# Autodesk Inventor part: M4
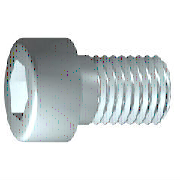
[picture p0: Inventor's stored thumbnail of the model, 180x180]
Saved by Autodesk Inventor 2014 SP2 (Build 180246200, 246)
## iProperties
IsCustomPart: 0
Created: 2016-04
Part Number: M4
Material: 강철, 연강
Description: 6각머리 태핑 나사
Document SubType Name: Modeling
Standard: KS B 1003
Designer: mdu
Standards Organization: KS
Language: ko-KR
Size Designation: M 4 x 10
Categories: <MemberInstance><Categories><Category DisplayName="조임쇠" InternalName="e4da775c-781d-43d5-af7c-5136215cf5a6" Mnemonic="FSTN"><Category DisplayName="볼트" InternalN
Density: 7.86 g/cm^3
Mass: 2.0371 g
Surface Area: 3.0572 cm^2
Volume: 0.259174 cm^3
Appearance: 금속 1800F 열
Author: mdu
Revision Number: 1
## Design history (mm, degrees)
sketch "스케치1"
  geometry: L1 (-1, 0)-(10, 0); L2 (10, 0)-(10, 2); L3 (10, 2)-(1.75, 2); L4 (1.75, 2)-(1.32, 2); L5 (1.32, 2)-(0, 2); L6 (0, 2)-(0, 3.5); L7 (0, 3.5)-(-4, 3.5); L8 (-4, 3.5)-(-4, 1.732); L9 (-4, 1.732)-(-2, 1.732); L10 (-2, 1.732)-(-1, 0); L11 (-6.8, 0)-(12.8, 0) reference; L12 (0, -0.7)-(0, 4.2) reference; L13 (1.75, 2)-(0, 2)
  constraints: 22 end point, 6 parallel, 2 collinear, 2 perpendicular, 1 horizontal, 1 point on line
  dimensions: "d1" = 8.25 distance from line of L3.end L2 (= GEL); "d2" = 0.42952 distance of L4.end L3.end (computed from GAL); "d3" = 4 distance between parallel lines of L8 L6 (= KOH); "d4" = 2 distance of L8.end L9.end (= INTI); "d5" = 60 deg angle of L10 L1; "d6" = 4 diameter of L3 L1 (= GD); "d7" = 4 diameter of L5 L1 (= BDM); "d8" = 3.4641 diameter of L9 L1 (= 1.1547 x SW); "d9" = 7 diameter of L7 L1 (= KOD); "d26" = 10 distance between parallel lines of L12 L2 (= NLG)
revolve "본체" sketch "스케치1" stored, may be unused: angle "d10" = 90 deg
sketch "스케치2"
  geometry: L1 (0, -4.9)-(0, 4.9) reference; L2 (-4.9, 0)-(4.9, 0) reference; L3 (1.732, 0)-(0.866, -1.5); L4 (0.866, -1.5)-(-0.866, -1.5); L5 (-0.866, -1.5)-(-1.732, 0); L6 (-1.732, 0)-(-0.866, 1.5); L7 (-0.866, 1.5)-(0.866, 1.5); L8 (0.866, 1.5)-(1.732, 0); 2 further points
  constraints: 12 end point, 1 coincident, 1 horizontal alignment, 1 point on line, 12 other
extrude "슬롯" join sketch "스케치2" stored distance "d11" = 10; taper "d12" = 0 deg
workplane "Work Plane1"
fillet "Fillet2" dims "d30" = 0.1 (= R)
body "Solid1"
fillet "모깎기1" dims "d17" = 0.4 (= RR)
feature "스레드" dims "d13" = 8.25 (= GEL), "d14" = 0
chamfer "모따기1" distance "d15" = 0.42941 (= -0.5 x SPD + 0.5 x GD); stored, may be unused: second distance "d16" = 0.42941 (= GUL), angle "d27" = 45 deg
other parameters: "GD" = 4 (= NND) [user parameter; used in 2 equation terms], "NLG" = 10 [user parameter; used in 1 equation term], "GEL" = 8.25 [user parameter; used in 2 equation terms], "KOD" = 7 [user parameter; used in 1 equation term], "KOH" = 4 [user parameter; used in 1 equation term], "INTI" = 2 [user parameter; used in 1 equation term], "GAL" = 0.42941 (= 0.61345 x PTC) [user parameter; used in 1 equation term], "GUL" = 0.42941 (= 0.61345 x PTC) [user parameter; used in 1 equation term], "BDM" = 4 (= NND) [user parameter; used in 1 equation term], "SW" = 3 [user parameter; used in 2 equation terms], "RR" = 0.4 [user parameter; used in 1 equation term], "SPD" = 3.14117 (= NND - 1.2269 x PTC) [user parameter; used in 1 equation term], "d19" = 0, "d28" = 0, "d29" = 0, "R" = 0.1 [user parameter; used in 1 equation term], "PHH" = 0.2 [user parameter], "GD1" = 3.14117 (= THREADDIA - 1.2269 x PTC) [user parameter], "THREADDIA" = 4 [user parameter; used in 1 equation term], "FAWI" = 45 deg [user parameter], "TPU" = 14.28571 (computed from PTC) [user parameter], "PTC" = 0.7 [user parameter; used in 5 equation terms], "NND" = 4 [user parameter; used in 3 equation terms], "TOA" = 30 deg [user parameter], "E0" = 3.465 (= 1.155 x SW) [user parameter]
